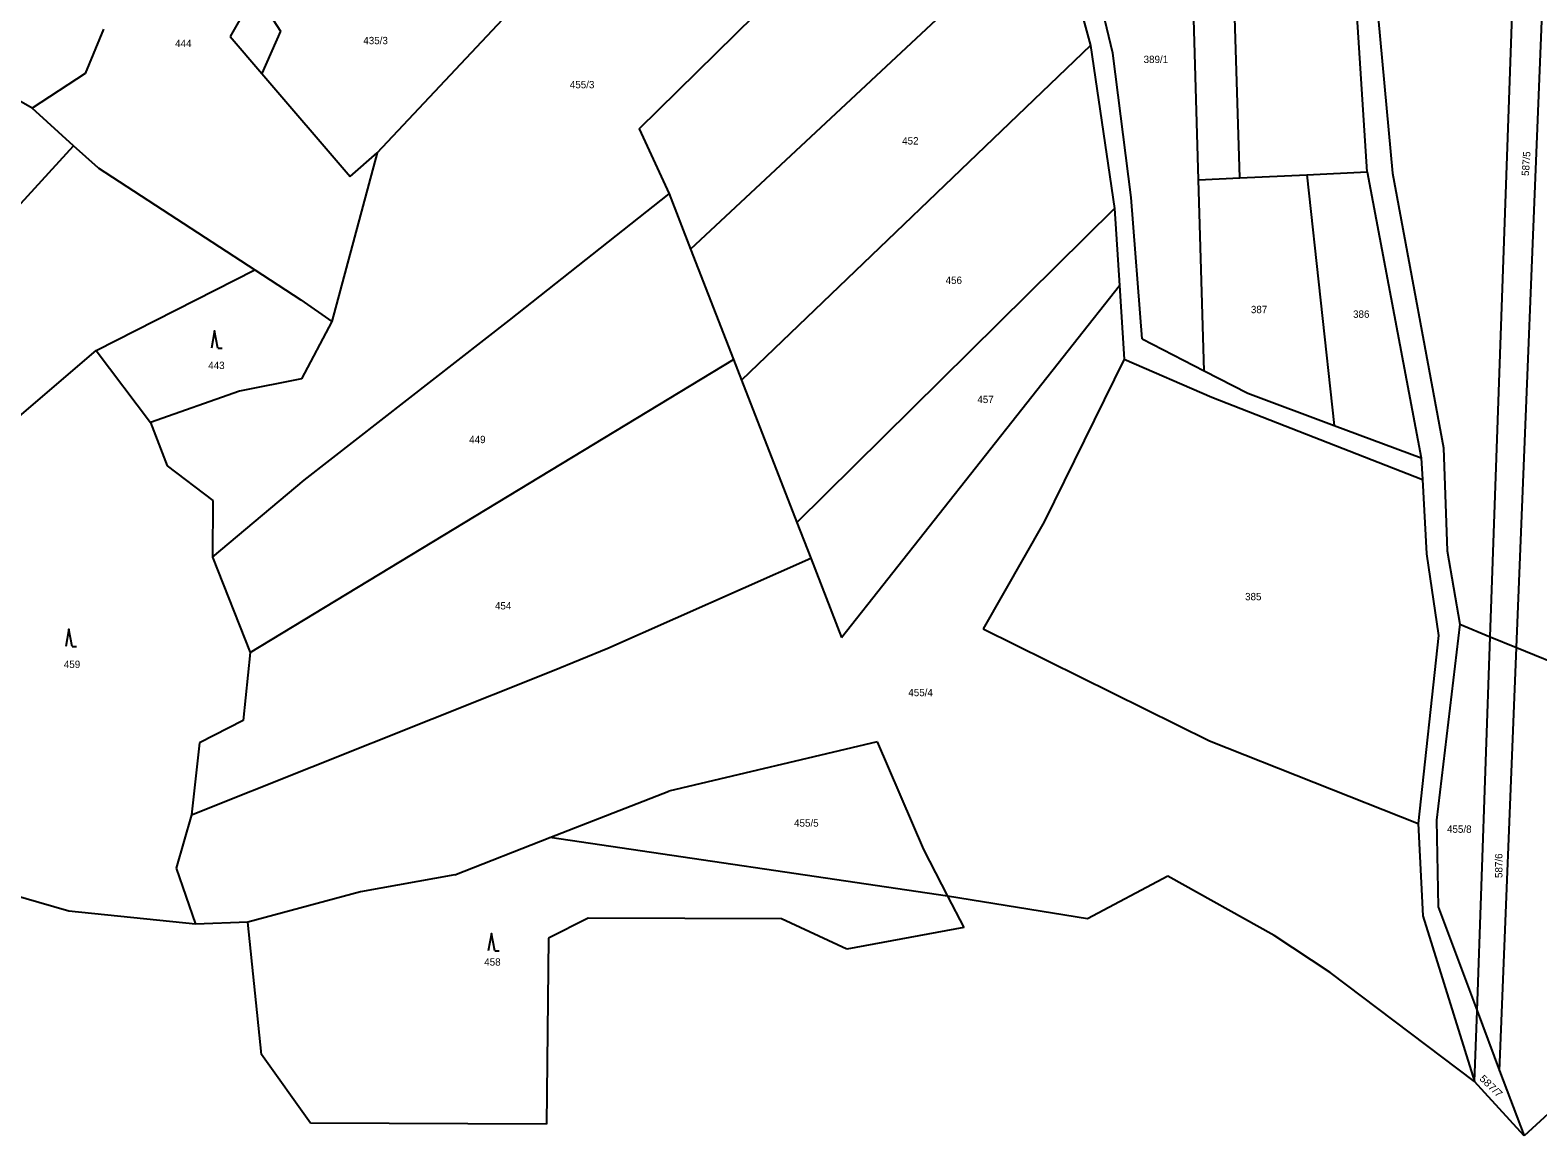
# Model space of a CAD drawing. Extents: x -664548 to -662415, y -1069720 to -1068208.
# Drawn here: x -663871.7 to -663522.5, y -1069653.8 to -1069397.8 of the extents above; entities that cross this region are included whole.
import ezdxf

# ---------------------------------------------------------------- set-up
doc = ezdxf.new("R2010")
doc.units = 0
doc.header["$LTSCALE"] = 0.68
doc.layers.add('1', color=7, linetype='Continuous', lineweight=25)
doc.layers.add('3', color=7, linetype='Continuous', lineweight=25)
doc.layers.add('2', color=7, linetype='Continuous')

msp = doc.modelspace()

# ---------------------------------------------------------------- linework, layer by layer
at = {"layer": '1'}
for p, q in [((-663533.54, -1069538.23), (-663525.71, -1069315.33)), ((-663601.1, -1069432.51), (-663604.26, -1069325.38)), ((-663591.5, -1069432.04), (-663594.75, -1069329.92)), ((-663730.63, -1069420.68), (-663649.12, -1069340.38)), ((-663562.07, -1069430.61), (-663567.74, -1069341.82)), ((-663564.14, -1069344.05), (-663556.21, -1069430.9)), ((-663799.35, -1069353.72), (-663825.36, -1069399.27)), ((-663718.73, -1069448.55), (-663634.92, -1069370.21)), ((-663633.89, -1069372.36), (-663626.15, -1069401.37)), ((-663527.43, -1069540.73), (-663520.83, -1069375.97)), ((-663620.97, -1069403.18), (-663624.79, -1069386.91)), ((-663819.27, -1069389.47), (-663813.67, -1069398.07)), ((-663791.3, -1069426.25), (-663758.57, -1069391.42)), ((-663854.69, -1069397.6), (-663858.93, -1069407.87)), ((-663825.36, -1069399.27), (-663818, -1069407.86)), ((-663813.67, -1069398.07), (-663818, -1069407.86)), ((-663871.25, -1069415.91), (-663899, -1069399.83)), ((-663626.15, -1069401.37), (-663706.94, -1069478.87)), ((-663626.15, -1069401.37), (-663620.54, -1069439.1)), ((-663616.69, -1069436.57), (-663620.97, -1069403.18)), ((-663858.93, -1069407.87), (-663871.25, -1069415.91)), ((-663818, -1069407.86), (-663797.6, -1069431.67)), ((-663861.66, -1069424.58), (-663871.25, -1069415.91)), ((-663730.63, -1069420.68), (-663723.71, -1069435.73)), ((-663898.67, -1069465.05), (-663861.66, -1069424.58)), ((-663855.96, -1069429.72), (-663861.66, -1069424.58)), ((-663791.3, -1069426.25), (-663801.79, -1069465.3)), ((-663797.6, -1069431.67), (-663791.3, -1069426.25)), ((-663855.96, -1069429.72), (-663819.63, -1069453.35)), ((-663576.02, -1069431.29), (-663562.07, -1069430.61)), ((-663562.07, -1069430.61), (-663549.5, -1069496.85)), ((-663601.1, -1069432.51), (-663591.5, -1069432.04)), ((-663599.8, -1069476.68), (-663601.1, -1069432.51)), ((-663591.5, -1069432.04), (-663576.02, -1069431.29)), ((-663576.02, -1069431.29), (-663569.71, -1069489.32)), ((-663556.21, -1069430.9), (-663544.37, -1069494.52)), ((-663760.64, -1069464.99), (-663723.71, -1069435.73)), ((-663723.71, -1069435.73), (-663718.73, -1069448.55)), ((-663614.14, -1069469.31), (-663616.69, -1069436.57)), ((-663694.12, -1069511.83), (-663620.54, -1069439.1)), ((-663620.54, -1069439.1), (-663619.39, -1069456.95)), ((-663718.73, -1069448.55), (-663708.81, -1069474.06)), ((-663856.36, -1069471.98), (-663819.63, -1069453.35)), ((-663819.63, -1069453.35), (-663809, -1069460.26)), ((-663683.78, -1069538.42), (-663619.39, -1069456.95)), ((-663619.39, -1069456.95), (-663618.3, -1069473.98)), ((-663809, -1069460.26), (-663801.79, -1069465.3)), ((-663801.79, -1069465.3), (-663808.84, -1069478.51)), ((-663808.24, -1069502.03), (-663760.64, -1069464.99)), ((-663881.76, -1069493.65), (-663856.36, -1069471.98)), ((-663856.36, -1069471.98), (-663843.79, -1069488.66)), ((-663614.14, -1069469.31), (-663599.8, -1069476.68)), ((-663820.74, -1069541.89), (-663708.81, -1069474.06)), ((-663708.81, -1069474.06), (-663706.94, -1069478.87)), ((-663618.3, -1069473.98), (-663636.86, -1069511.68)), ((-663618.3, -1069473.98), (-663598.05, -1069482.76)), ((-663808.84, -1069478.51), (-663823.18, -1069481.39)), ((-663706.94, -1069478.87), (-663694.12, -1069511.83)), ((-663599.8, -1069476.68), (-663589.68, -1069481.88)), ((-663823.18, -1069481.39), (-663843.79, -1069488.66)), ((-663598.05, -1069482.76), (-663549.23, -1069501.83)), ((-663589.68, -1069481.88), (-663569.71, -1069489.32)), ((-663843.79, -1069488.66), (-663839.93, -1069498.7)), ((-663569.71, -1069489.32), (-663549.5, -1069496.85)), ((-663549.5, -1069496.85), (-663549.23, -1069501.83)), ((-663544.37, -1069494.52), (-663543.49, -1069518.33)), ((-663839.93, -1069498.7), (-663829.35, -1069506.69)), ((-663829.42, -1069519.79), (-663808.24, -1069502.03)), ((-663549.23, -1069501.83), (-663548.28, -1069519.03)), ((-663829.35, -1069506.69), (-663829.42, -1069519.79)), ((-663694.12, -1069511.83), (-663690.91, -1069520.08)), ((-663636.86, -1069511.68), (-663650.98, -1069536.38)), ((-663829.42, -1069519.79), (-663820.74, -1069541.89)), ((-663737.92, -1069540.86), (-663690.91, -1069520.08)), ((-663690.91, -1069520.08), (-663683.78, -1069538.42)), ((-663548.28, -1069519.03), (-663545.55, -1069537.97)), ((-663543.49, -1069518.33), (-663540.59, -1069535.34)), ((-663540.59, -1069535.34), (-663546.01, -1069580.7)), ((-663540.59, -1069535.34), (-663533.54, -1069538.23)), ((-663650.98, -1069536.38), (-663598.58, -1069562.33)), ((-663545.55, -1069537.97), (-663550.25, -1069581.49)), ((-663536.58, -1069624.82), (-663533.54, -1069538.23)), ((-663533.54, -1069538.23), (-663527.43, -1069540.73)), ((-663820.74, -1069541.89), (-663822.37, -1069557.64)), ((-663750.7, -1069546.16), (-663737.92, -1069540.86)), ((-663531.36, -1069638.74), (-663527.43, -1069540.73)), ((-663527.43, -1069540.73), (-663489.83, -1069556.13)), ((-663834.34, -1069579.44), (-663750.7, -1069546.16)), ((-663822.37, -1069557.64), (-663832.45, -1069562.81)), ((-663832.45, -1069562.81), (-663834.34, -1069579.44)), ((-663675.56, -1069562.57), (-663723.75, -1069573.97)), ((-663675.56, -1069562.57), (-663664.77, -1069587.47)), ((-663598.58, -1069562.33), (-663550.25, -1069581.49)), ((-663751.33, -1069584.75), (-663723.75, -1069573.97)), ((-663834.34, -1069579.44), (-663837.87, -1069591.79)), ((-663546.01, -1069580.7), (-663545.63, -1069600.73)), ((-663550.25, -1069581.49), (-663549.12, -1069602.83)), ((-663862.74, -1069601.74), (-663914.77, -1069586.75)), ((-663773.33, -1069593.34), (-663751.33, -1069584.75)), ((-663659.22, -1069598.3), (-663751.33, -1069584.75)), ((-663664.77, -1069587.47), (-663659.22, -1069598.3)), ((-663837.87, -1069591.79), (-663833.38, -1069604.77)), ((-663608.2, -1069593.69), (-663626.82, -1069603.55)), ((-663583.56, -1069607.43), (-663608.2, -1069593.69)), ((-663659.22, -1069598.3), (-663655.49, -1069605.58)), ((-663626.82, -1069603.55), (-663659.22, -1069598.3)), ((-663833.38, -1069604.77), (-663862.74, -1069601.74)), ((-663545.63, -1069600.73), (-663536.58, -1069624.82)), ((-663821.24, -1069604.31), (-663833.38, -1069604.77)), ((-663818.12, -1069634.96), (-663821.24, -1069604.31)), ((-663742.44, -1069603.4), (-663751.67, -1069608.03)), ((-663697.68, -1069603.55), (-663742.44, -1069603.4)), ((-663682.52, -1069610.55), (-663697.68, -1069603.55)), ((-663549.12, -1069602.83), (-663537.16, -1069641.22)), ((-663751.67, -1069608.03), (-663752.08, -1069651.09)), ((-663655.49, -1069605.58), (-663682.52, -1069610.55)), ((-663570.61, -1069615.98), (-663583.56, -1069607.43)), ((-663537.16, -1069641.22), (-663570.61, -1069615.98)), ((-663806.77, -1069650.85), (-663818.12, -1069634.96)), ((-663531.36, -1069638.74), (-663525.71, -1069653.77)), ((-663508.35, -1069637.87), (-663525.71, -1069653.77)), ((-663534.77, -1069643.85), (-663537.16, -1069641.22)), ((-663525.71, -1069653.77), (-663534.77, -1069643.85)), ((-663752.08, -1069651.09), (-663806.77, -1069650.85))]:
    msp.add_line(p, q, dxfattribs=at)
for points in [[(-663773.33, -1069593.34), (-663795.19, -1069597.27), (-663821.24, -1069604.31)], [(-663537.16, -1069641.22), (-663536.58, -1069624.82), (-663531.36, -1069638.74)]]:
    msp.add_lwpolyline(points, dxfattribs=at)
at = {"layer": '3'}
for p, q in [((-663828.22, -1069471.45), (-663827.224, -1069471.45)), ((-663861.96, -1069540.52), (-663860.964, -1069540.52)), ((-663764.1, -1069610.92), (-663763.104, -1069610.92))]:
    msp.add_line(p, q, dxfattribs=at)
for points in [[(-663828.22, -1069471.45), (-663828.97, -1069467.45), (-663829.72, -1069471.45)], [(-663861.96, -1069540.52), (-663862.71, -1069536.52), (-663863.46, -1069540.52)], [(-663764.1, -1069610.92), (-663764.85, -1069606.92), (-663765.6, -1069610.92)]]:
    msp.add_lwpolyline(points, dxfattribs=at)

# ---------------------------------------------------------------- texts
at = {"layer": '2'}
for s, p in [('435/3', (-663794.53, -1069401.084)), ('444', (-663838.12, -1069401.765)), ('389/1', (-663613.82, -1069405.445)), ('455/3', (-663746.7, -1069411.285)), ('452', (-663669.74, -1069424.304)), ('456', (-663659.67, -1069456.574)), ('387', (-663588.97, -1069463.344)), ('386', (-663565.31, -1069464.415)), ('443', (-663830.44, -1069476.275)), ('457', (-663652.32, -1069484.155)), ('449', (-663770.01, -1069493.435)), ('385', (-663590.32, -1069529.795)), ('454', (-663764.04, -1069531.925)), ('459', (-663863.88, -1069545.475)), ('455/4', (-663668.31, -1069552.005)), ('455/5', (-663694.77, -1069582.205)), ('455/8', (-663543.55, -1069583.625)), ('458', (-663766.52, -1069614.375))]:
    msp.add_text(s, height=1.7, dxfattribs=at).set_placement(p)
for s, rotation, p in [('587/5', 86, (-663524.596, -1069431.629)), ('587/6', 90, (-663530.715, -1069594.09))]:
    msp.add_text(s, height=1.7, rotation=rotation, dxfattribs=at).set_placement(p)
at = {"layer": '2', "width": 1.1}
msp.add_text('587/7', height=1.7, rotation=316, dxfattribs=at).set_placement((-663536.195, -1069640.695))

doc.saveas('drawing.dxf')
